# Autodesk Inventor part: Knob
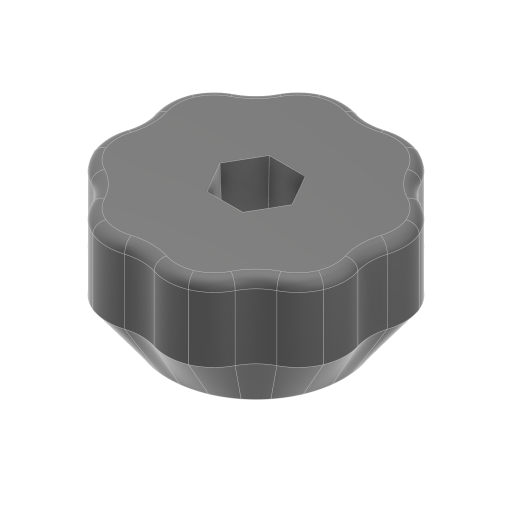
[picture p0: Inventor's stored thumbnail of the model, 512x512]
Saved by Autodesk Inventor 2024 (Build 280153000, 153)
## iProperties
Created: 2024-06
Part Number: Knob
Material: PET Plastic
Document SubType Name: Modeling
Designer: simon
Density: 1.541 g/cm^3
Appearance: Smooth - Black
Author: simon
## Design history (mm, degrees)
sketch "Sketch1"
  geometry: L1 (46.052, 0)-(-46.052, 0) reference; A1 r 25 centre (0, 0) between (22.978, 9.849) and (22.978, -9.849); A2 r 10 centre (13.787, 5.909) between (23.34, 2.955) and (22.978, 9.849); A3 r 10 centre (32.894, 0) between (23.34, 2.955) and (23.34, -2.955); A4 r 10 centre (13.787, -5.909) between (22.978, -9.849) and (23.34, -2.955); A5 r 10 centre (5.57, 13.927) between (14.415, 18.593) and (9.284, 23.212); A6 r 10 centre (23.26, 23.26) between (14.415, 18.593) and (18.593, 14.415); A7 r 10 centre (13.927, 5.57) between (23.212, 9.284) and (18.593, 14.415); A8 r 10 centre (-5.909, 13.787) between (-2.955, 23.34) and (-9.849, 22.978); A9 r 10 centre (0, 32.894) between (-2.955, 23.34) and (2.955, 23.34); A10 r 10 centre (5.909, 13.787) between (9.849, 22.978) and (2.955, 23.34); A11 r 10 centre (-13.927, 5.57) between (-18.593, 14.415) and (-23.212, 9.284); A12 r 10 centre (-23.26, 23.26) between (-18.593, 14.415) and (-14.415, 18.593); A13 r 10 centre (-5.57, 13.927) between (-9.284, 23.212) and (-14.415, 18.593); A14 r 10 centre (-13.787, -5.909) between (-23.34, -2.955) and (-22.978, -9.849); A15 r 10 centre (-32.894, 0) between (-23.34, -2.955) and (-23.34, 2.955); A16 r 10 centre (-13.787, 5.909) between (-22.978, 9.849) and (-23.34, 2.955); A17 r 10 centre (-5.57, -13.927) between (-14.415, -18.593) and (-9.284, -23.212); A18 r 10 centre (-23.26, -23.26) between (-14.415, -18.593) and (-18.593, -14.415); A19 r 10 centre (-13.927, -5.57) between (-23.212, -9.284) and (-18.593, -14.415); A20 r 10 centre (5.909, -13.787) between (2.955, -23.34) and (9.849, -22.978); A21 r 10 centre (0, -32.894) between (2.955, -23.34) and (-2.955, -23.34); A22 r 10 centre (-5.909, -13.787) between (-9.849, -22.978) and (-2.955, -23.34); A23 r 10 centre (13.927, -5.57) between (18.593, -14.415) and (23.212, -9.284); A24 r 10 centre (23.26, -23.26) between (18.593, -14.415) and (14.415, -18.593); A25 r 10 centre (5.57, -13.927) between (9.284, -23.212) and (14.415, -18.593); 9 further points
  constraints: 50 point on circle, 25 centre point, 4 tangent, 2 equal radius, 1 coincident, 1 point on line, 81 other
  dimensions: "d0" = 50 diameter of A1; "d1" = 10 radius of A3; "d4" = 360 deg dimension on point (0, 0) A2.centre (derived)
extrude "Extrusion1" new body sketch "Sketch1" distance "d6" = 15; taper "d7" = 0 deg
sketch "Sketch2"
  geometry: C1 r 17.5 at (0, 0); 1 further point
  constraints: 1 centre point, 1 coincident
  dimensions: "d8" = 35 diameter of C1
extrude "Extrusion2" join sketch "Sketch2" distance "d9" = 10; taper "d10" = 0 deg
sketch "Sketch3"
  geometry: L1 (3.608, 6.25)-(7.217, 0); L2 (7.217, 0)-(3.608, -6.25); L3 (3.608, -6.25)-(-3.608, -6.25); L4 (-3.608, -6.25)-(-7.217, 0); L5 (-7.217, 0)-(-3.608, 6.25); L6 (-3.608, 6.25)-(3.608, 6.25); 2 further points
  constraints: 12 end point, 1 coincident, 13 other
  dimensions: "d11" = 12.5 distance between parallel lines of L3 L6
extrude "Extrusion3" cut sketch "Sketch3" distance "d12" = 15; taper "d13" = -2 deg
sketch "Sketch4"
  geometry: C1 r 4 at (0, 0); 1 further point
  constraints: 1 centre point, 1 coincident
  dimensions: "d14" = 8 diameter of C1
extrude "Extrusion4" cut sketch "Sketch4" extent not by distance; stored distance "d15" = 0; taper "d16" = 0 deg
sketch "Sketch5"
  geometry: L1 (-3.306, 5.726)-(-6.612, 0) reference; L2 (-6.612, 0)-(-3.306, -5.726) reference; L3 (-3.306, -5.726)-(3.306, -5.726) reference; L4 (3.306, -5.726)-(6.612, 0) reference; L5 (6.612, 0)-(3.306, 5.726) reference; L6 (3.306, 5.726)-(-3.306, 5.726) reference; C1 r 17.5 at (0, 0) reference; C2 r 4 at (0, 0) reference; A1 r 10 centre (-23.26, 23.26) between (-18.593, 14.415) and (-14.415, 18.593) reference; A2 r 10 centre (-5.57, 13.927) between (-9.566, 23.094) and (-14.415, 18.593) reference; A3 r 10 centre (-5.909, 13.787) between (-2.955, 23.34) and (-9.566, 23.094) reference; A4 r 10 centre (0, 32.894) between (-2.955, 23.34) and (2.955, 23.34) reference; A5 r 10 centre (5.909, 13.787) between (9.566, 23.094) and (2.955, 23.34) reference; A6 r 10 centre (5.57, 13.927) between (14.415, 18.593) and (9.566, 23.094) reference; A7 r 10 centre (23.26, 23.26) between (14.415, 18.593) and (18.593, 14.415) reference; A8 r 10 centre (13.927, 5.57) between (23.094, 9.566) and (18.593, 14.415) reference; A9 r 10 centre (13.787, 5.909) between (23.34, 2.955) and (23.094, 9.566) reference; A10 r 10 centre (32.894, 0) between (23.34, 2.955) and (23.34, -2.955) reference; A11 r 10 centre (13.787, -5.909) between (23.094, -9.566) and (23.34, -2.955) reference; A12 r 10 centre (13.927, -5.57) between (18.593, -14.415) and (23.094, -9.566) reference; A13 r 10 centre (23.26, -23.26) between (18.593, -14.415) and (14.415, -18.593) reference; A14 r 10 centre (5.57, -13.927) between (9.566, -23.094) and (14.415, -18.593) reference; A15 r 10 centre (5.909, -13.787) between (2.955, -23.34) and (9.566, -23.094) reference; A16 r 10 centre (0, -32.894) between (2.955, -23.34) and (-2.955, -23.34) reference; A17 r 10 centre (-5.909, -13.787) between (-9.566, -23.094) and (-2.955, -23.34) reference; A18 r 10 centre (-5.57, -13.927) between (-14.415, -18.593) and (-9.566, -23.094) reference; A19 r 10 centre (-23.26, -23.26) between (-14.415, -18.593) and (-18.593, -14.415) reference; A20 r 10 centre (-13.927, -5.57) between (-23.094, -9.566) and (-18.593, -14.415) reference; A21 r 10 centre (-13.787, -5.909) between (-23.34, -2.955) and (-23.094, -9.566) reference; A22 r 10 centre (-32.894, 0) between (-23.34, -2.955) and (-23.34, 2.955) reference; A23 r 10 centre (-13.787, 5.909) between (-23.094, 9.566) and (-23.34, 2.955) reference; A24 r 10 centre (-13.927, 5.57) between (-18.593, 14.415) and (-23.094, 9.566) reference; 1 further point
  node "Project Cut Edges1"
sketch "Sketch6"
  geometry: C1 r 4 at (0, 0) reference; C2 r 17.5 at (0, 0) reference; 1 further point
  node "Project Cut Edges2"
loft "Loft1" dims "d17" = 0, "d18" = 90 deg, "d19" = 0, "d20" = 90 deg
  node "Edges1"
  node "Edges2"
fillet "Fillet1" dims "d21" = 2
body "Solid1"
